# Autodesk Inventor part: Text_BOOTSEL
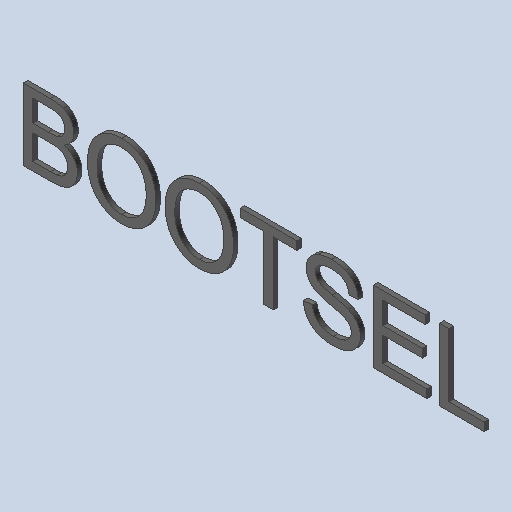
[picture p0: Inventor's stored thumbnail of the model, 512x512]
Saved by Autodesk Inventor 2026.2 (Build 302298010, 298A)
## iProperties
Created: 2026-10
Part Number: Text_BOOTSEL
Material: Générique
Document SubType Name: Modeling
Designer: mel
Density: 1 g/cm^3
Appearance: Par défaut
Author: mel
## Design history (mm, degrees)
feature "Base1"
feature "Base2"
feature "Base3"
feature "Base4"
feature "Base5"
feature "Base6"
feature "Base7"
node "Solide1"
node "Solide2"
node "Solide3"
node "Solide4"
node "Solide5"
node "Solide6"
node "Solide7"
